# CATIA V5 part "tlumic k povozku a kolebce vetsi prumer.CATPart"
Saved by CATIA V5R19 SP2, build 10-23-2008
Part number: tlumic k povozku a kolebce vetsi prumer
Bounding box of the stored display mesh (mm): x -300 to 167.668, y -60 to 60, z -50 to 50
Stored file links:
  C:\Users\Martiin\Desktop\9.semestr\Projekt-diplomka\3D model\tlumic k povozku a kolebce vetsi prumer.CATPart
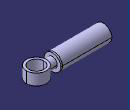
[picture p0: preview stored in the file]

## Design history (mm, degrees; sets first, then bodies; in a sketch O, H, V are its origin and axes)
Body1 (main body)
  Sketch1 on yz-plane, origin (0, 0, 0), H (0, 1, 0), V (0, 0, 1)
    circle A1 centre (0, 0) radius 50
    radius A1 = 50
  Pad1: profile Sketch1, direction (1, 0, 0), length 10
  Sketch2 on start face of Pad1, origin (0, 0, 0), H (0, -1, 0), V (0, 0, 1)
    circle A1 centre (0, 0) radius 40
    point P1 (0, 40)
    circle A2 centre (0, 0) radius 50
    radius A1 = 40
    radius A2 = 50
    coincidence: A1 P1, P1 V
  Pad2: profile Sketch2, direction (-1, 0, 0), length 300
  Sketch3 on xy-plane, origin (0, 0, 0), H (1, 0, 0), V (0, 1, 0)
    circle A1 centre (107.6684, 0) radius 45
    point P1 (107.6684, 0)
    circle A2 centre (107.6684, 0) radius 60
    radius A2 = 60
    radius A1 = 45
    coincidence: P1 H
  Pad3: profile Sketch3, direction (0, 0, 1), length 34, mirrored extent
  Sketch4 on end face of Pad1, origin (10, 0, 0), H (0, 1, 0), V (0, 0, 1)
    circle A1 centre (0, 0) radius 30
    point P1 (0, 30)
    radius A1 = 30
    coincidence: A1 P1, P1 V
  Pad4: profile Sketch4, direction (1, 0, 0), up to the existing solid (limit type 2)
